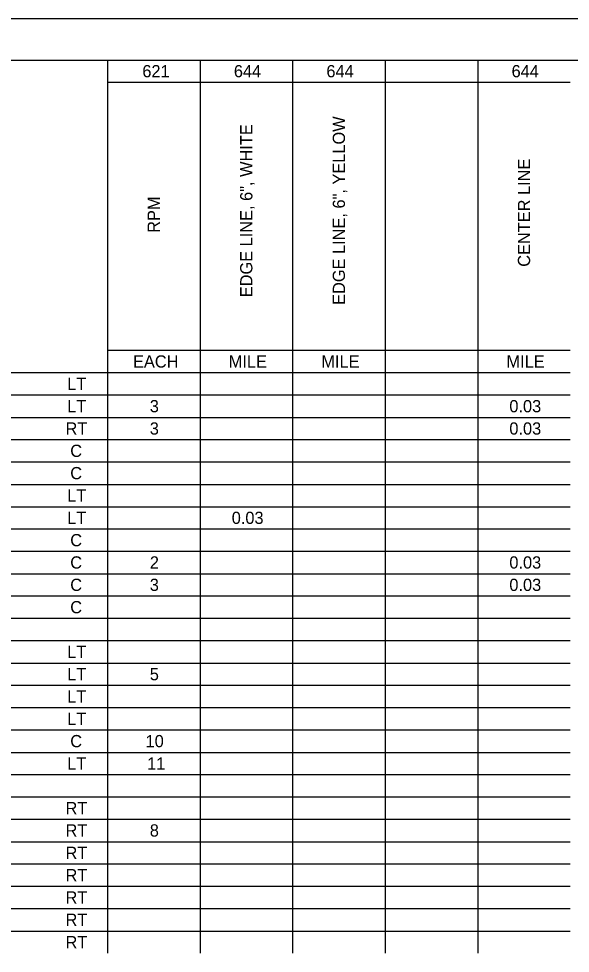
# Model space of a CAD drawing. Extents: x 0 to 34, y 0 to 22.
# Drawn here: x 7.41 to 14.09, y 10.69 to 22 of the extents above; entities that cross this region are included whole.
import ezdxf

# ---------------------------------------------------------------- set-up
doc = ezdxf.new("R2010")
doc.units = 0
for name, color, linetype in [('SH_Border', 7, 'Continuous'), ('SH_Cut_Line', 7, 'Continuous'), ('SH_Data', 7, 'Continuous')]:
    doc.layers.add(name, color=color, linetype=linetype)

msp = doc.modelspace()

# ---------------------------------------------------------------- linework, layer by layer
at = {"layer": 'SH_Border'}
msp.add_lwpolyline([(1.5, 21.5), (33.5, 21.5), (33.5, 0.5), (1.5, 0.5)], close=True, dxfattribs=at)
at = {"layer": 'SH_Cut_Line'}
msp.add_lwpolyline([(0, 0), (34, 0), (34, 22), (0, 22)], close=True, dxfattribs=at)
at = {"layer": 'SH_Data'}
for p, q in [((6.249, 21.5), (7.716, 21.5)), ((7.716, 21.5), (10.727, 21.5)), ((8.488, 21.5), (8.488, 21.23)), ((9.608, 21.5), (9.608, 21.23)), ((10.727, 21.5), (11.847, 21.5)), ((10.727, 21.5), (10.727, 21.23)), ((11.847, 21.5), (14.086, 21.5)), ((11.847, 21.5), (11.847, 21.23)), ((12.966, 21.5), (12.966, 21.23)), ((8.488, 21.23), (10.727, 21.23)), ((8.488, 21.23), (8.488, 20.96)), ((9.608, 21.23), (9.608, 20.96)), ((10.727, 21.23), (11.847, 21.23)), ((10.727, 21.23), (10.727, 20.96)), ((11.847, 21.23), (14.086, 21.23)), ((11.847, 21.23), (11.847, 20.96)), ((12.966, 21.23), (12.966, 20.96)), ((8.488, 20.96), (8.488, 20.69)), ((9.608, 20.96), (9.608, 20.69)), ((10.727, 20.96), (10.727, 20.69)), ((11.847, 20.96), (11.847, 20.69)), ((12.966, 20.96), (12.966, 20.69)), ((8.488, 20.69), (8.488, 20.419)), ((9.608, 20.69), (9.608, 20.419)), ((10.727, 20.69), (10.727, 20.419)), ((11.847, 20.69), (11.847, 20.419)), ((12.966, 20.69), (12.966, 20.419)), ((8.488, 20.419), (8.488, 20.149)), ((9.608, 20.419), (9.608, 20.149)), ((10.727, 20.419), (10.727, 20.149)), ((11.847, 20.419), (11.847, 20.149)), ((12.966, 20.419), (12.966, 20.149)), ((8.488, 20.149), (8.488, 19.879)), ((9.608, 20.149), (9.608, 19.879)), ((10.727, 20.149), (10.727, 19.879)), ((11.847, 20.149), (11.847, 19.879)), ((12.966, 20.149), (12.966, 19.879)), ((8.488, 19.879), (8.488, 19.609)), ((9.608, 19.879), (9.608, 19.609)), ((10.727, 19.879), (10.727, 19.609)), ((11.847, 19.879), (11.847, 19.609)), ((12.966, 19.879), (12.966, 19.609)), ((8.488, 19.609), (8.488, 19.338)), ((9.608, 19.609), (9.608, 19.338)), ((10.727, 19.609), (10.727, 19.338)), ((11.847, 19.609), (11.847, 19.338)), ((12.966, 19.609), (12.966, 19.338)), ((8.488, 19.338), (8.488, 19.068)), ((9.608, 19.338), (9.608, 19.068)), ((10.727, 19.338), (10.727, 19.068)), ((11.847, 19.338), (11.847, 19.068)), ((12.966, 19.338), (12.966, 19.068)), ((8.488, 19.068), (8.488, 18.798)), ((9.608, 19.068), (9.608, 18.798)), ((10.727, 19.068), (10.727, 18.798)), ((11.847, 19.068), (11.847, 18.798)), ((12.966, 19.068), (12.966, 18.798)), ((8.488, 18.798), (8.488, 18.528)), ((9.608, 18.798), (9.608, 18.528)), ((10.727, 18.798), (10.727, 18.528)), ((11.847, 18.798), (11.847, 18.528)), ((12.966, 18.798), (12.966, 18.528)), ((8.488, 18.528), (8.488, 18.257)), ((9.608, 18.528), (9.608, 18.257)), ((10.727, 18.528), (10.727, 18.257)), ((11.847, 18.528), (11.847, 18.257)), ((12.966, 18.528), (12.966, 18.257)), ((8.488, 18.257), (8.488, 17.987)), ((9.608, 18.257), (9.608, 17.987)), ((10.727, 18.257), (10.727, 17.987)), ((11.847, 18.257), (11.847, 17.987)), ((12.966, 18.257), (12.966, 17.987)), ((8.488, 17.987), (10.727, 17.987)), ((8.488, 17.987), (8.488, 17.717)), ((9.608, 17.987), (9.608, 17.717)), ((10.727, 17.987), (11.847, 17.987)), ((10.727, 17.987), (10.727, 17.717)), ((11.847, 17.987), (14.086, 17.987)), ((11.847, 17.987), (11.847, 17.717)), ((12.966, 17.987), (12.966, 17.717)), ((6.249, 17.717), (7.716, 17.717)), ((7.716, 17.717), (10.727, 17.717)), ((8.488, 17.717), (8.488, 17.447)), ((9.608, 17.717), (9.608, 17.447)), ((10.727, 17.717), (11.847, 17.717)), ((10.727, 17.717), (10.727, 17.447)), ((11.847, 17.717), (14.086, 17.717)), ((11.847, 17.717), (11.847, 17.447)), ((12.966, 17.717), (12.966, 17.447)), ((6.249, 17.447), (7.716, 17.447)), ((7.716, 17.447), (10.727, 17.447)), ((8.488, 17.447), (8.488, 17.176)), ((9.608, 17.447), (9.608, 17.176)), ((10.727, 17.447), (11.847, 17.447)), ((10.727, 17.447), (10.727, 17.176)), ((11.847, 17.447), (14.086, 17.447)), ((11.847, 17.447), (11.847, 17.176)), ((12.966, 17.447), (12.966, 17.176)), ((6.249, 17.176), (7.716, 17.176)), ((7.716, 17.176), (10.727, 17.176)), ((8.488, 17.176), (8.488, 16.906)), ((9.608, 17.176), (9.608, 16.906)), ((10.727, 17.176), (11.847, 17.176)), ((10.727, 17.176), (10.727, 16.906)), ((11.847, 17.176), (14.086, 17.176)), ((11.847, 17.176), (11.847, 16.906)), ((12.966, 17.176), (12.966, 16.906)), ((6.249, 16.906), (7.716, 16.906)), ((7.716, 16.906), (10.727, 16.906)), ((8.488, 16.906), (8.488, 16.636)), ((9.608, 16.906), (9.608, 16.636)), ((10.727, 16.906), (11.847, 16.906)), ((10.727, 16.906), (10.727, 16.636)), ((11.847, 16.906), (14.086, 16.906)), ((11.847, 16.906), (11.847, 16.636)), ((12.966, 16.906), (12.966, 16.636)), ((6.249, 16.636), (7.716, 16.636)), ((7.716, 16.636), (10.727, 16.636)), ((8.488, 16.636), (8.488, 16.365)), ((9.608, 16.636), (9.608, 16.365)), ((10.727, 16.636), (11.847, 16.636)), ((10.727, 16.636), (10.727, 16.365)), ((11.847, 16.636), (14.086, 16.636)), ((11.847, 16.636), (11.847, 16.365)), ((12.966, 16.636), (12.966, 16.365)), ((6.249, 16.365), (7.716, 16.365)), ((7.716, 16.365), (10.727, 16.365)), ((8.488, 16.365), (8.488, 16.095)), ((9.608, 16.365), (9.608, 16.095)), ((10.727, 16.365), (11.847, 16.365)), ((10.727, 16.365), (10.727, 16.095)), ((11.847, 16.365), (14.086, 16.365)), ((11.847, 16.365), (11.847, 16.095)), ((12.966, 16.365), (12.966, 16.095)), ((6.249, 16.095), (7.716, 16.095)), ((7.716, 16.095), (10.727, 16.095)), ((8.488, 16.095), (8.488, 15.825)), ((9.608, 16.095), (9.608, 15.825)), ((10.727, 16.095), (11.847, 16.095)), ((10.727, 16.095), (10.727, 15.825)), ((11.847, 16.095), (14.086, 16.095)), ((11.847, 16.095), (11.847, 15.825)), ((12.966, 16.095), (12.966, 15.825)), ((6.249, 15.825), (7.716, 15.825)), ((7.716, 15.825), (10.727, 15.825)), ((8.488, 15.825), (8.488, 15.555)), ((9.608, 15.825), (9.608, 15.555)), ((10.727, 15.825), (11.847, 15.825)), ((10.727, 15.825), (10.727, 15.555)), ((11.847, 15.825), (14.086, 15.825)), ((11.847, 15.825), (11.847, 15.555)), ((12.966, 15.825), (12.966, 15.555)), ((6.249, 15.555), (7.716, 15.555)), ((7.716, 15.555), (10.727, 15.555)), ((8.488, 15.555), (8.488, 15.284)), ((9.608, 15.555), (9.608, 15.284)), ((10.727, 15.555), (11.847, 15.555)), ((10.727, 15.555), (10.727, 15.284)), ((11.847, 15.555), (14.086, 15.555)), ((11.847, 15.555), (11.847, 15.284)), ((12.966, 15.555), (12.966, 15.284)), ((6.249, 15.284), (7.716, 15.284)), ((7.716, 15.284), (10.727, 15.284)), ((8.488, 15.284), (8.488, 15.014)), ((9.608, 15.284), (9.608, 15.014)), ((10.727, 15.284), (11.847, 15.284)), ((10.727, 15.284), (10.727, 15.014)), ((11.847, 15.284), (14.086, 15.284)), ((11.847, 15.284), (11.847, 15.014)), ((12.966, 15.284), (12.966, 15.014)), ((6.249, 15.014), (7.716, 15.014)), ((7.716, 15.014), (10.727, 15.014)), ((8.488, 15.014), (8.488, 14.744)), ((9.608, 15.014), (9.608, 14.744)), ((10.727, 15.014), (11.847, 15.014)), ((10.727, 15.014), (10.727, 14.744)), ((11.847, 15.014), (14.086, 15.014)), ((11.847, 15.014), (11.847, 14.744)), ((12.966, 15.014), (12.966, 14.744)), ((6.249, 14.744), (7.716, 14.744)), ((7.716, 14.744), (10.727, 14.744)), ((8.488, 14.744), (8.488, 14.474)), ((9.608, 14.744), (9.608, 14.474)), ((10.727, 14.744), (11.847, 14.744)), ((10.727, 14.744), (10.727, 14.474)), ((11.847, 14.744), (14.086, 14.744)), ((11.847, 14.744), (11.847, 14.474)), ((12.966, 14.744), (12.966, 14.474)), ((6.249, 14.474), (7.716, 14.474)), ((7.716, 14.474), (10.727, 14.474)), ((8.488, 14.474), (8.488, 14.203)), ((9.608, 14.474), (9.608, 14.203)), ((10.727, 14.474), (11.847, 14.474)), ((10.727, 14.474), (10.727, 14.203)), ((11.847, 14.474), (14.086, 14.474)), ((11.847, 14.474), (11.847, 14.203)), ((12.966, 14.474), (12.966, 14.203)), ((6.249, 14.203), (7.716, 14.203)), ((7.716, 14.203), (10.727, 14.203)), ((8.488, 14.203), (8.488, 13.933)), ((9.608, 14.203), (9.608, 13.933)), ((10.727, 14.203), (11.847, 14.203)), ((10.727, 14.203), (10.727, 13.933)), ((11.847, 14.203), (14.086, 14.203)), ((11.847, 14.203), (11.847, 13.933)), ((12.966, 14.203), (12.966, 13.933)), ((6.249, 13.933), (7.716, 13.933)), ((7.716, 13.933), (10.727, 13.933)), ((8.488, 13.933), (8.488, 13.663)), ((9.608, 13.933), (9.608, 13.663)), ((10.727, 13.933), (11.847, 13.933)), ((10.727, 13.933), (10.727, 13.663)), ((11.847, 13.933), (14.086, 13.933)), ((11.847, 13.933), (11.847, 13.663)), ((12.966, 13.933), (12.966, 13.663)), ((6.249, 13.663), (7.716, 13.663)), ((7.716, 13.663), (10.727, 13.663)), ((8.488, 13.663), (8.488, 13.393)), ((9.608, 13.663), (9.608, 13.393)), ((10.727, 13.663), (11.847, 13.663)), ((10.727, 13.663), (10.727, 13.393)), ((11.847, 13.663), (14.086, 13.663)), ((11.847, 13.663), (11.847, 13.393)), ((12.966, 13.663), (12.966, 13.393)), ((6.249, 13.393), (7.716, 13.393)), ((7.716, 13.393), (10.727, 13.393)), ((8.488, 13.393), (8.488, 13.122)), ((9.608, 13.393), (9.608, 13.122)), ((10.727, 13.393), (11.847, 13.393)), ((10.727, 13.393), (10.727, 13.122)), ((11.847, 13.393), (14.086, 13.393)), ((11.847, 13.393), (11.847, 13.122)), ((12.966, 13.393), (12.966, 13.122)), ((6.249, 13.122), (7.716, 13.122)), ((7.716, 13.122), (10.727, 13.122)), ((8.488, 13.122), (8.488, 12.852)), ((9.608, 13.122), (9.608, 12.852)), ((10.727, 13.122), (11.847, 13.122)), ((10.727, 13.122), (10.727, 12.852)), ((11.847, 13.122), (14.086, 13.122)), ((11.847, 13.122), (11.847, 12.852)), ((12.966, 13.122), (12.966, 12.852)), ((6.249, 12.852), (7.716, 12.852)), ((7.716, 12.852), (10.727, 12.852)), ((8.488, 12.852), (8.488, 12.582)), ((9.608, 12.852), (9.608, 12.582)), ((10.727, 12.852), (11.847, 12.852)), ((10.727, 12.852), (10.727, 12.582)), ((11.847, 12.852), (14.086, 12.852)), ((11.847, 12.852), (11.847, 12.582)), ((12.966, 12.852), (12.966, 12.582)), ((6.249, 12.582), (7.716, 12.582)), ((7.716, 12.582), (10.727, 12.582)), ((8.488, 12.582), (8.488, 12.312)), ((9.608, 12.582), (9.608, 12.312)), ((10.727, 12.582), (11.847, 12.582)), ((10.727, 12.582), (10.727, 12.312)), ((11.847, 12.582), (14.086, 12.582)), ((11.847, 12.582), (11.847, 12.312)), ((12.966, 12.582), (12.966, 12.312)), ((6.249, 12.312), (7.716, 12.312)), ((7.716, 12.312), (10.727, 12.312)), ((8.488, 12.312), (8.488, 12.041)), ((9.608, 12.312), (9.608, 12.041)), ((10.727, 12.312), (11.847, 12.312)), ((10.727, 12.312), (10.727, 12.041)), ((11.847, 12.312), (14.086, 12.312)), ((11.847, 12.312), (11.847, 12.041)), ((12.966, 12.312), (12.966, 12.041)), ((6.249, 12.041), (7.716, 12.041)), ((7.716, 12.041), (10.727, 12.041)), ((8.488, 12.041), (8.488, 11.771)), ((9.608, 12.041), (9.608, 11.771)), ((10.727, 12.041), (11.847, 12.041)), ((10.727, 12.041), (10.727, 11.771)), ((11.847, 12.041), (14.086, 12.041)), ((11.847, 12.041), (11.847, 11.771)), ((12.966, 12.041), (12.966, 11.771)), ((6.249, 11.771), (7.716, 11.771)), ((7.716, 11.771), (10.727, 11.771)), ((8.488, 11.771), (8.488, 11.501)), ((9.608, 11.771), (9.608, 11.501)), ((10.727, 11.771), (11.847, 11.771)), ((10.727, 11.771), (10.727, 11.501)), ((11.847, 11.771), (14.086, 11.771)), ((11.847, 11.771), (11.847, 11.501)), ((12.966, 11.771), (12.966, 11.501)), ((6.249, 11.501), (7.716, 11.501)), ((7.716, 11.501), (10.727, 11.501)), ((8.488, 11.501), (8.488, 11.231)), ((9.608, 11.501), (9.608, 11.231)), ((10.727, 11.501), (11.847, 11.501)), ((10.727, 11.501), (10.727, 11.231)), ((11.847, 11.501), (14.086, 11.501)), ((11.847, 11.501), (11.847, 11.231)), ((12.966, 11.501), (12.966, 11.231)), ((6.249, 11.231), (7.716, 11.231)), ((7.716, 11.231), (10.727, 11.231)), ((8.488, 11.231), (8.488, 10.96)), ((9.608, 11.231), (9.608, 10.96)), ((10.727, 11.231), (11.847, 11.231)), ((10.727, 11.231), (10.727, 10.96)), ((11.847, 11.231), (14.086, 11.231)), ((11.847, 11.231), (11.847, 10.96)), ((12.966, 11.231), (12.966, 10.96)), ((6.249, 10.96), (7.716, 10.96)), ((7.716, 10.96), (10.727, 10.96)), ((8.488, 10.96), (8.488, 10.69)), ((9.608, 10.96), (9.608, 10.69)), ((10.727, 10.96), (11.847, 10.96)), ((10.727, 10.96), (10.727, 10.69)), ((11.847, 10.96), (14.086, 10.96)), ((11.847, 10.96), (11.847, 10.69)), ((12.966, 10.96), (12.966, 10.69))]:
    msp.add_line(p, q, dxfattribs=at)

# ---------------------------------------------------------------- texts
for s, p in [('621', (8.91, 21.291)), ('644', (10.017, 21.291)), ('644', (11.136, 21.291)), ('644', (13.376, 21.291)), ('EACH', (8.797, 17.778)), ('MILE', (9.955, 17.778)), ('MILE', (11.075, 17.778)), ('MILE', (13.314, 17.778)), ('LT', (8.002, 17.508)), ('LT', (8.002, 17.237)), ('3', (9, 17.237)), ('0.03', (13.349, 17.237)), ('RT', (7.981, 16.967)), ('3', (9, 16.967)), ('0.03', (13.349, 16.967)), ('C', (8.038, 16.697)), ('C', (8.038, 16.427)), ('LT', (8.002, 16.156)), ('LT', (8.002, 15.886)), ('0.03', (9.991, 15.886)), ('C', (8.038, 15.616)), ('C', (8.038, 15.346)), ('2', (9.001, 15.346)), ('0.03', (13.349, 15.346)), ('C', (8.038, 15.075)), ('3', (9, 15.075)), ('0.03', (13.349, 15.075)), ('C', (8.038, 14.805)), ('LT', (8.002, 14.265)), ('LT', (8.002, 13.994)), ('5', (9, 13.994)), ('LT', (8.002, 13.724)), ('LT', (8.002, 13.454)), ('C', (8.038, 13.184)), ('10', (8.949, 13.184)), ('LT', (8.002, 12.913)), ('11', (8.968, 12.913)), ('RT', (7.981, 12.373)), ('RT', (7.981, 12.103)), ('8', (9, 12.103)), ('RT', (7.981, 11.832)), ('RT', (7.981, 11.562)), ('RT', (7.981, 11.292)), ('RT', (7.981, 11.022)), ('RT', (7.981, 10.751))]:
    msp.add_text(s, height=0.148, dxfattribs=at).set_placement(p)
for s, p in [('EDGE LINE, 6", YELLOW', (11.361, 18.537)), ('EDGE LINE, 6", WHITE', (10.241, 18.629)), ('CENTER LINE', (13.6, 18.998)), ('RPM', (9.122, 19.409))]:
    msp.add_text(s, height=0.148, rotation=90, dxfattribs=at).set_placement(p)

doc.saveas('drawing.dxf')
